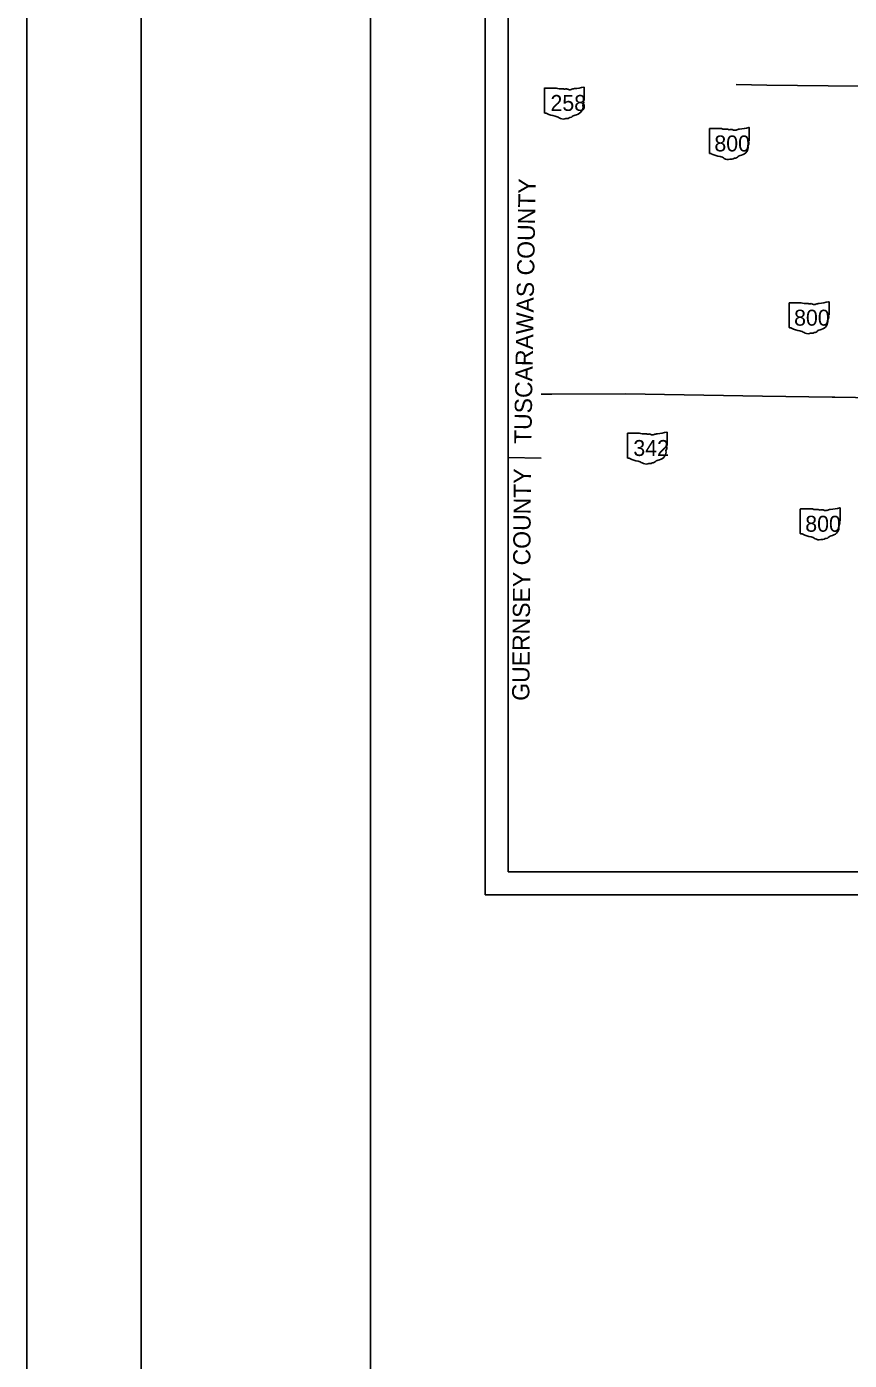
# Model space of a CAD drawing. Extents: x 0 to 70.6, y 0 to 31.9.
# Drawn here: x 0 to 3.59, y 11.97 to 17.79 of the extents above; entities that cross this region are included whole.
import ezdxf

# ---------------------------------------------------------------- set-up
doc = ezdxf.new("R2010")
doc.units = 0
for name, color, linetype in [('GM_X_County', 7, 'Continuous'), ('GM_X_County_Road_Text', 7, 'Continuous'), ('GM_X_County_ROW', 7, 'Continuous'), ('GM_X_Minor_River', 7, 'Continuous'), ('GM_X_Minor_River_Text', 7, 'Continuous'), ('GM_X_Section', 7, 'Continuous'), ('GM_X_Township', 7, 'Continuous')]:
    doc.layers.add(name, color=color, linetype=linetype)

msp = doc.modelspace()

# ---------------------------------------------------------------- linework, layer by layer
at = {"layer": 'GM_X_County'}
for points in [[(0.5, 21.5), (1.5, 21.5), (1.5, 0.5), (0.5, 0.5)], [(1.5, 21.5), (33.5, 21.5), (33.5, 0.5), (1.5, 0.5)]]:
    msp.add_lwpolyline(points, close=True, dxfattribs=at)
at = {"layer": 'GM_X_County_Road_Text'}
msp.add_line((2.2444, 15.9046), (2.1, 15.9081), dxfattribs=at)
at = {"layer": 'GM_X_County_ROW'}
msp.add_lwpolyline([(3.0949, 17.5353), (3.2293, 17.5323), (3.8985, 17.5257), (3.8919, 17.1438), (3.8881, 16.9409), (3.8731, 16.2595), (3.8722, 16.2095), (3.8718, 16.1664), (3.7972, 16.1673), (3.5262, 16.1717), (3.5138, 16.1718), (3.2094, 16.1759), (2.6123, 16.1864), (2.2906, 16.1846), (2.2448, 16.1852)], dxfattribs=at)
at = {"layer": 'GM_X_Minor_River_Text'}
for p, q in [((2.2584, 17.5187), (2.2584, 17.413)), ((2.3111, 17.5205), (2.2601, 17.5205)), ((2.4325, 17.4678), (2.4325, 17.5231)), ((2.4324, 17.4678), (2.4325, 17.4678)), ((2.9785, 17.342), (2.9785, 17.2363)), ((3.0312, 17.3438), (2.9802, 17.3438)), ((3.1525, 17.2912), (3.1525, 17.3464)), ((3.1525, 17.2912), (3.1525, 17.2912)), ((3.5003, 16.5308), (3.5003, 16.5861)), ((3.3263, 16.5817), (3.3263, 16.476)), ((3.379, 16.5835), (3.328, 16.5835)), ((3.5003, 16.5309), (3.5003, 16.5308)), ((2.6206, 16.013), (2.6206, 15.9073)), ((2.6732, 16.0148), (2.6223, 16.0148)), ((2.7946, 15.9621), (2.7946, 16.0174)), ((2.7946, 15.9622), (2.7946, 15.9621)), ((3.3749, 15.6825), (3.3749, 15.5769)), ((3.4276, 15.6844), (3.3766, 15.6844)), ((3.549, 15.6317), (3.549, 15.687)), ((3.5489, 15.6317), (3.549, 15.6317))]:
    msp.add_line(p, q, dxfattribs=at)
for centre, major_axis, start_param, end_param in [((2.2604, 17.5189), (0.00202, 0), 1.712693, 3.28349), ((2.3232, 17.5327), (0.0196, 0), 4.042523, 4.731795), ((2.3297, 17.4612), (0.0702, 0), 1.404758, 1.657858), ((2.3457, 17.5194), (0.00564, 0), 3.836095, 5.185415), ((2.3539, 17.5072), (0.0117, 0), 0.950623, 2.079405), ((2.394, 17.4882), (0.0371, 0), 1.699011, 2.107814), ((2.3705, 17.6645), (0.1845, 0), 4.814394, 5.042369), ((2.4305, 17.5233), (0.00194, 0), 6.141152, 7.989035), ((2.3691, 17.524), (0.0141, 0), 4.081561, 5.145723), ((2.432, 17.4638), (0.003, 0), 1.883978, 3.671073), ((2.4129, 17.4568), (0.018, 0), 5.934695, 6.695948), ((2.4304, 17.4676), (0.00207, 0), 5.05454, 6.418171), ((2.2604, 17.4128), (0.00203, 0), 3.00124, 4.508301), ((2.2608, 17.4236), (0.0155, 0), 4.665946, 4.897461), ((2.2639, 17.4069), (0.0056, 0), 0.519207, 1.627899), ((2.3346, 17.5018), (0.1333, 0), 4.195997, 4.488961), ((2.4003, 17.3833), (0.0253, 0), 1.647645, 2.488434), ((2.3808, 17.4377), (0.0462, 0), 5.101752, 6.440018), ((2.4394, 17.4447), (0.0131, 0), 2.387724, 3.262537), ((2.2949, 17.3655), (0.0417, 0), 0.823519, 1.323587), ((2.34, 17.4064), (0.0265, 0), 4.026481, 4.996735), ((2.3552, 17.3698), (0.0217, 0), 1.495662, 1.94098), ((2.3572, 17.3985), (0.0141, 0), 4.691044, 5.507374), ((2.3699, 17.3882), (0.00397, 0), 1.147584, 2.315152), ((2.3682, 17.4028), (0.0149, 0), 4.937069, 5.64225), ((2.9805, 17.3422), (0.00202, 0), 1.712693, 3.28349), ((3.0433, 17.3561), (0.0196, 0), 4.042523, 4.731795), ((3.0905, 17.4879), (0.1845, 0), 4.814394, 5.042369), ((3.1506, 17.3467), (0.00194, 0), 6.141152, 7.989035), ((3.0498, 17.2845), (0.0702, 0), 1.404758, 1.657858), ((3.0657, 17.3428), (0.00564, 0), 3.836095, 5.185415), ((3.074, 17.3306), (0.0117, 0), 0.950623, 2.079405), ((3.0891, 17.3473), (0.0141, 0), 4.081561, 5.145723), ((3.1141, 17.3115), (0.0371, 0), 1.699011, 2.107814), ((3.1521, 17.2871), (0.003, 0), 1.883978, 3.671073), ((3.133, 17.2801), (0.018, 0), 5.934695, 6.695948), ((3.1504, 17.2909), (0.00207, 0), 5.05454, 6.418171), ((2.9805, 17.2361), (0.00203, 0), 3.00124, 4.508301), ((2.9808, 17.2469), (0.0155, 0), 4.665946, 4.897461), ((2.984, 17.2302), (0.0056, 0), 0.519207, 1.627899), ((3.0546, 17.3252), (0.1333, 0), 4.195997, 4.488961), ((3.1203, 17.2067), (0.0253, 0), 1.647645, 2.488434), ((3.1009, 17.261), (0.0462, 0), 5.101752, 6.440018), ((3.1595, 17.268), (0.0131, 0), 2.387724, 3.262537), ((3.0149, 17.1889), (0.0417, 0), 0.823519, 1.323587), ((3.06, 17.2297), (0.0265, 0), 4.026481, 4.996735), ((3.0753, 17.1932), (0.0217, 0), 1.495662, 1.94098), ((3.0772, 17.2218), (0.0141, 0), 4.691044, 5.507374), ((3.09, 17.2116), (0.00397, 0), 1.147584, 2.315152), ((3.0883, 17.2261), (0.0149, 0), 4.937069, 5.64225), ((3.4383, 16.7276), (0.1845, 0), 4.814394, 5.042369), ((3.4984, 16.5863), (0.00194, 0), 6.141152, 7.989035), ((3.3283, 16.5819), (0.00202, 0), 1.712693, 3.28349), ((3.3911, 16.5958), (0.0196, 0), 4.042523, 4.731795), ((3.3976, 16.5242), (0.0702, 0), 1.404758, 1.657858), ((3.4135, 16.5825), (0.00564, 0), 3.836095, 5.185415), ((3.4218, 16.5702), (0.0117, 0), 0.950623, 2.079405), ((3.437, 16.587), (0.0141, 0), 4.081561, 5.145723), ((3.4619, 16.5512), (0.0371, 0), 1.699011, 2.107814), ((3.4999, 16.5268), (0.003, 0), 1.883978, 3.671073), ((3.4983, 16.5306), (0.00207, 0), 5.05454, 6.418171), ((3.3283, 16.4758), (0.00203, 0), 3.00124, 4.508301), ((3.3286, 16.4866), (0.0155, 0), 4.665946, 4.897461), ((3.3318, 16.4699), (0.0056, 0), 0.519207, 1.627899), ((3.4025, 16.5649), (0.1333, 0), 4.195997, 4.488961), ((3.4487, 16.5007), (0.0462, 0), 5.101752, 6.440018), ((3.5073, 16.5077), (0.0131, 0), 2.387724, 3.262537), ((3.4808, 16.5198), (0.018, 0), 5.934695, 6.695948), ((3.3627, 16.4285), (0.0417, 0), 0.823519, 1.323587), ((3.4078, 16.4694), (0.0265, 0), 4.026481, 4.996735), ((3.4231, 16.4329), (0.0217, 0), 1.495662, 1.94098), ((3.4251, 16.4615), (0.0141, 0), 4.691044, 5.507374), ((3.4378, 16.4512), (0.00397, 0), 1.147584, 2.315152), ((3.4361, 16.4658), (0.0149, 0), 4.937069, 5.64225), ((3.4681, 16.4463), (0.0253, 0), 1.647645, 2.488434), ((2.6225, 16.0132), (0.00202, 0), 1.712693, 3.28349), ((2.6854, 16.0271), (0.0196, 0), 4.042523, 4.731795), ((2.6918, 15.9555), (0.0702, 0), 1.404758, 1.657858), ((2.7078, 16.0138), (0.00564, 0), 3.836095, 5.185415), ((2.7161, 16.0015), (0.0117, 0), 0.950623, 2.079405), ((2.7312, 16.0183), (0.0141, 0), 4.081561, 5.145723), ((2.7561, 15.9825), (0.0371, 0), 1.699011, 2.107814), ((2.7326, 16.1589), (0.1845, 0), 4.814394, 5.042369), ((2.7926, 16.0176), (0.00194, 0), 6.141152, 7.989035), ((2.8015, 15.939), (0.0131, 0), 2.387724, 3.262537), ((2.7941, 15.9581), (0.003, 0), 1.883978, 3.671073), ((2.7751, 15.9511), (0.018, 0), 5.934695, 6.695948), ((2.7925, 15.9619), (0.00207, 0), 5.05454, 6.418171), ((2.6226, 15.9071), (0.00203, 0), 3.00124, 4.508301), ((2.6229, 15.9179), (0.0155, 0), 4.665946, 4.897461), ((2.626, 15.9012), (0.0056, 0), 0.519207, 1.627899), ((2.6967, 15.9962), (0.1333, 0), 4.195997, 4.488961), ((2.657, 15.8598), (0.0417, 0), 0.823519, 1.323587), ((2.7304, 15.8971), (0.0149, 0), 4.937069, 5.64225), ((2.7624, 15.8777), (0.0253, 0), 1.647645, 2.488434), ((2.7429, 15.932), (0.0462, 0), 5.101752, 6.440018), ((2.7021, 15.9007), (0.0265, 0), 4.026481, 4.996735), ((2.7174, 15.8642), (0.0217, 0), 1.495662, 1.94098), ((2.7193, 15.8928), (0.0141, 0), 4.691044, 5.507374), ((2.732, 15.8825), (0.00397, 0), 1.147584, 2.315152), ((3.3769, 15.6828), (0.00202, 0), 1.712693, 3.28349), ((3.4397, 15.6966), (0.0196, 0), 4.042523, 4.731795), ((3.4462, 15.625), (0.0702, 0), 1.404758, 1.657858), ((3.4622, 15.6833), (0.00564, 0), 3.836095, 5.185415), ((3.4704, 15.6711), (0.0117, 0), 0.950623, 2.079405), ((3.4856, 15.6879), (0.0141, 0), 4.081561, 5.145723), ((3.5105, 15.6521), (0.0371, 0), 1.699011, 2.107814), ((3.487, 15.8284), (0.1845, 0), 4.814394, 5.042369), ((3.547, 15.6872), (0.00194, 0), 6.141152, 7.989035), ((3.4973, 15.6015), (0.0462, 0), 5.101752, 6.440018), ((3.5559, 15.6086), (0.0131, 0), 2.387724, 3.262537), ((3.5485, 15.6276), (0.003, 0), 1.883978, 3.671073), ((3.5294, 15.6207), (0.018, 0), 5.934695, 6.695948), ((3.5469, 15.6315), (0.00207, 0), 5.05454, 6.418171), ((3.3769, 15.5766), (0.00203, 0), 3.00124, 4.508301), ((3.3773, 15.5875), (0.0155, 0), 4.665946, 4.897461), ((3.3804, 15.5708), (0.0056, 0), 0.519207, 1.627899), ((3.4511, 15.6657), (0.1333, 0), 4.195997, 4.488961), ((3.4114, 15.5294), (0.0417, 0), 0.823519, 1.323587), ((3.4565, 15.5703), (0.0265, 0), 4.026481, 4.996735), ((3.4717, 15.5337), (0.0217, 0), 1.495662, 1.94098), ((3.4737, 15.5623), (0.0141, 0), 4.691044, 5.507374), ((3.4864, 15.5521), (0.00397, 0), 1.147584, 2.315152), ((3.4847, 15.5666), (0.0149, 0), 4.937069, 5.64225), ((3.5168, 15.5472), (0.0253, 0), 1.647645, 2.488434)]:
    msp.add_ellipse(centre, major_axis=major_axis, ratio=0.8, start_param=start_param, end_param=end_param, dxfattribs=at)
at = {"layer": 'GM_X_Section'}
msp.add_lwpolyline([(0, 0), (34, 0), (34, 22), (0, 22)], close=True, dxfattribs=at)
at = {"layer": 'GM_X_Township'}
for p, q in [((2, 21), (2, 14)), ((2.1, 20.9), (2.1, 14.1)), ((2.1, 14.1), (8.9, 14.1)), ((2, 14), (9, 14))]:
    msp.add_line(p, q, dxfattribs=at)

# ---------------------------------------------------------------- texts
at = {"layer": 'GM_X_Minor_River'}
for s, rotation, p in [('TUSCARAWAS COUNTY', 89.04481, (2.2017, 15.9666)), ('GUERNSEY COUNTY', 89.56996, (2.1926, 14.8463))]:
    msp.add_text(s, height=0.075, rotation=rotation, dxfattribs=at).set_placement(p)
at = {"layer": 'GM_X_Minor_River_Text'}
for s, p in [('258', (2.285, 17.4204)), ('800', (3, 17.2438)), ('800', (3.3478, 16.4835)), ('342', (2.6465, 15.9148)), ('800', (3.3965, 15.5843))]:
    msp.add_text(s, height=0.06961, dxfattribs=at).set_placement(p)

doc.saveas('drawing.dxf')
